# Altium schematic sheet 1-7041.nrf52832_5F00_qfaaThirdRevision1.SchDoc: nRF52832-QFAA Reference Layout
size A4; Revision: 1.1; SheetNumber: 1; SheetTotal: 1; DrawnBy: RUBR/KJP; DocumentSize: A4; PCAName: nRF52832-QFAA Reference Layout
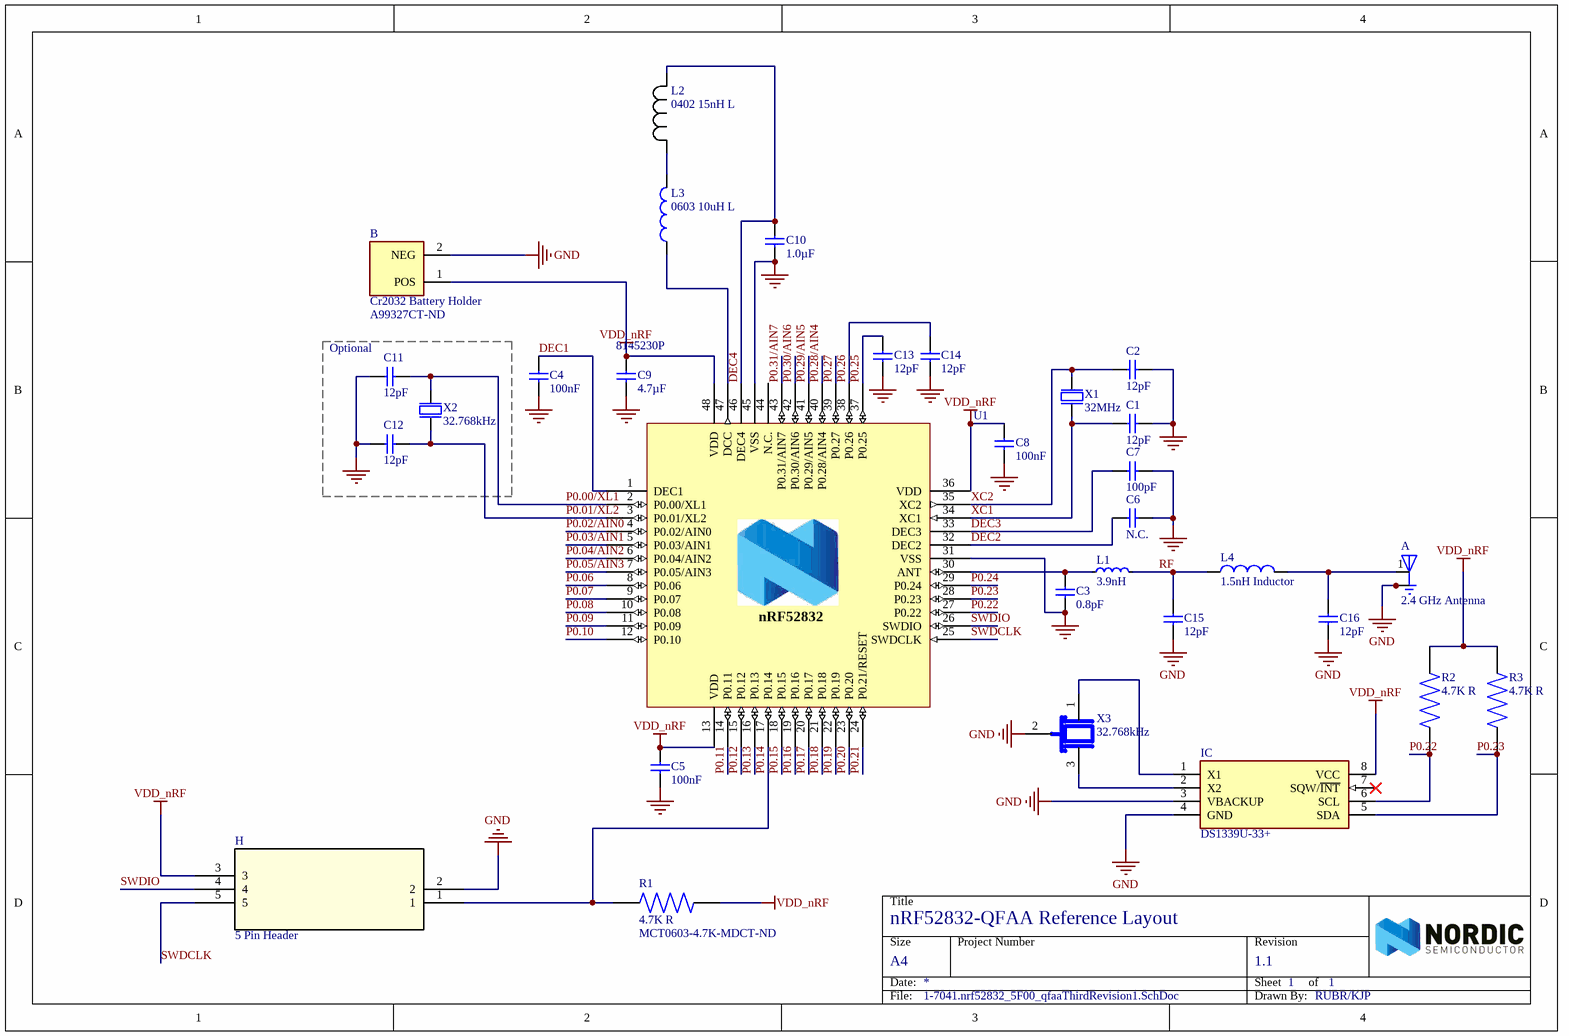
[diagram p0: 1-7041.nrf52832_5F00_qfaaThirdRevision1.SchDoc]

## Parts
A  2.4 GHz Antenna  [XDCR_2450AT42E010BE]
B  Cr2032 Battery Holder  Supplier Part Number 1: A99327CT-ND  [TE_796136-1]
C1  12pF  [CAPC1005X04L]
C2  12pF  [CAPC1005X04L]
C3  0.8pF  [CAPC1005X04L]
C4  100nF  [CAPC1005X04L]
C5  100nF  [CAPC1005X04L]
C6  N.C.  [CAPC1005X04L]
C7  100pF  [CAPC1005X04L]
C8  100nF  [CAPC1005X04L]
C9  4.7µF  Supplier Part Number 1: 8145230P  [CAPC1608X06L]
C10  1.0µF  [CAPC1608X06L]
C11  12pF  [CAPC1005X04L]
C12  12pF  [CAPC1005X04L]
C13  12pF  [CAPC1005X04L]
C14  12pF  [CAPC1005X04L]
C15  12pF  [CAPC1005X04L]
C16  12pF  [CAPC1005X04L]
H  5 Pin Header  [22-28-4052]
IC  DS1339U-33+  [SOP65P490X110-8N]
L1  3.9nH  [INDC1005X04L]
L2  0402 15nH L  [IND_1005_TDK]
L3  0603 10uH L  [INDC1608X100N]
L4  1.5nH Inductor  [INDC1005X55N]
R1  4.7K R  Supplier Part Number 1: MCT0603-4.7K-MDCT-ND  [RESC1508X55N]
R2  4.7K R  [RESC1508X55N]
R3  4.7K R  [RESC1508X55N]
U1  nRF52832-QFAA  [QFN40P600X600X90-48N]  (value not drawn)
X1  32MHz  [BT-XTAL_2016]
X2  32.768kHz  [XTAL_3215]
X3  32.768kHz  [XTAL_ECS-.327-6-1210B-N-TR]

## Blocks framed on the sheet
Optional: C11 C12 X2

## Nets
GND: A.3(GND) A.4(GND) B.2(NEG) C1.2 C2.2 C3.1 C4.2 C5.2 C6.1 C7.2 C8.2 C9.2 C10.1 C11.2 C12.2 C13.2 C14.2 C15.1 C16.1 H.2 IC.3(VBACKUP) IC.4(GND) U1.31(VSS) U1.45(VSS) U1.49(GND) X1.2(GND) X1.4(GND) X3.2(GND)
VDD_nRF: B.1(POS) C5.1 C8.1 C9.1 H.3 IC.8(VCC) R1.2 R2.2 R3.2 U1.13(VDD) U1.36(VDD) U1.48(VDD)
DEC1: C4.1 U1.1(DEC1)
DEC2: C6.2 U1.32(DEC2)
DEC3: C7.1 U1.33(DEC3)
DEC4: C10.2 L2.1 U1.46(DEC4)
P0.00/XL1: C11.1 U1.2(P0.00/XL1) X2.1(inp)
P0.01/XL2: C12.1 U1.3(P0.01/XL2) X2.2(out)
P0.02/AIN0: U1.4(P0.02/AIN0)
P0.03/AIN1: U1.5(P0.03/AIN1)
P0.04/AIN2: U1.6(P0.04/AIN2)
P0.05/AIN3: U1.7(P0.05/AIN3)
P0.06: U1.8(P0.06)
P0.07: U1.9(P0.07)
P0.08: U1.10(P0.08)
P0.09: U1.11(P0.09)
P0.10: U1.12(P0.10)
P0.11: U1.14(P0.11)
P0.12: U1.15(P0.12)
P0.13: U1.16(P0.13)
P0.14: H.1 R1.1 U1.17(P0.14)
P0.15: U1.18(P0.15)
P0.16: U1.19(P0.16)
P0.17: U1.20(P0.17)
P0.18: U1.21(P0.18)
P0.19: U1.22(P0.19)
P0.20: U1.23(P0.20)
P0.21: U1.24(P0.21/RESET)
P0.22: IC.6(SCL) R2.1 U1.27(P0.22)
P0.23: IC.5(SDA) R3.1 U1.28(P0.23)
P0.24: U1.29(P0.24)
P0.25: C13.1 U1.37(P0.25)
P0.26: C14.1 U1.38(P0.26)
P0.27: U1.39(P0.27)
P0.28/AIN4: U1.40(P0.28/AIN4)
P0.29/AIN5: U1.41(P0.29/AIN5)
P0.30/AIN6: U1.42(P0.30/AIN6)
P0.31/AIN7: U1.43(P0.31/AIN7)
RF: C15.2 L1.2 L4.1
SWDCLK: H.5 U1.25(SWDCLK)
SWDIO: H.4 U1.26(SWDIO)
XC1: C1.1 U1.34(XC1) X1.1(inp)
XC2: C2.1 U1.35(XC2) X1.3(out)
NetA_1: A.1(FEEDING) C16.2 L4.2
NetC3_2: C3.2 L1.1 U1.30(ANT)
NetIC_1: IC.1(X1) X3.1(IN/OUT)
NetIC_2: IC.2(X2) X3.3(OUT/IN)
NetL2_2: L2.2 L3.2
NetL3_1: L3.1 U1.47(DCC)

Not connected (* = marked no-connect by the designer): IC 7(SQW/~{INT})*; U1 44(N.C.)

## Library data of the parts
A = 2450AT42E010BE: JOHANSON TECHNOLOGY - 2450AT42E010BE - Chip-Antenne, Einzelband, 2.4GHz, 50 Ohm, 5mm x 2mm x 1.5mm; Number of Bands: 1; Max Power Dissipation: 2W
B = 796136-1: Surface Mount Battery Holder For 1; Leaf Spring Contact; Number_of_Positions: 2; MF: TE Connectivity
C1 C2 C11 C13 C14 = C0402-12p: Capacitor, NP0, ±2%; Note: 50V; Artikkelnr Noca: 20029159; Artikkelnr Simpro: N.A.
C3 = C0402-0.8p: Capacitor, NP0, ±5%; Note: 50V; Artikkelnr Noca: 20029147; Artikkelnr Simpro: N.A.
C4 C5 C8 = C0402-100n: Capacitor, X7R, ±10%; Note: 16V; Artikkelnr Noca: 20039200; Artikkelnr Simpro: N.A.
C6 = C0402-N.C.: Not mounted; Note: Chip Cap; Artikkelnr Noca: N.A.
C7 = C0402-100p: Capacitor, NP0, ±5%; Note: 50V; Artikkelnr Noca: 20029135; Artikkelnr Simpro: N.A.
C9 = C0603-4µ7: Capacitor, X5R, ±10%; Note: 6.3V; Artikkelnr Noca: 20069060; Artikkelnr Simpro: N.A.
C10 = C0603-1µ0: Capacitor, X7R, ±10%; Note: 16V; Artikkelnr Noca: 20039335; Artikkelnr Simpro: N.A.
C12 = CAP: Capacitor, NP0, ±2%; Part Number: C0402-12p; Note: 50V; Artikkelnr Noca: 20029159; Artikkelnr Simpro: N.A.
C15 C16 = CAP_0402: CAP CER 12PF 50V C0G/NPO 0402; Part Number: C0402-12p; Artikkelnr Noca: 20029159; Artikkelnr Simpro: N.A.; Tolerance: 5%; Dielectric: C0G
H = 22-28-4052: CONN HEADER 5POS .100 VERT TIN; Manufacturer: Molex; Vendor: Molex Connector Corporation; Built_By: EMA_UL_Team; SourceLibrary: Molex_2012-01-01_KK_Breakaway; Number of Contacts: 5; Gender: Male; Contact Resistance: 20mR; Connector Type: Male Pin; Current Rating: 4A; Voltage Rating: 250V; Max Voltage Rating (DC): 250.25kV; Pitch: 2.54mm; Glow Wire Compliant: Non-compliant
IC = DS1339U-33+: Real Time Clock Serial 8-Pin uMAX T/R; Manufacturer_Name: Maxim Integrated; Manufacturer: Maxim; Manufacturer Part Number: DS1339U-33+T&R; Time Format: HH:MM:SS; Operating Supply Voltage: 3.3V; Max Supply Voltage: 5.5V; Min Supply Voltage: 2.97V; Interface: I2C,Serial,2-Wire; Date Format: YY-MM-DD-dd
L1 = L0402-3n9: High frequency chip inductor ±5%; Manufacturer: Murata; Manufacturer Part Number: LQP15MN3N9B02D; Artikkelnr Noca: 33029151; Artikkelnr Simpro: N.A.
L2 = MLK1005S15NJT000: Ind RF Chip Unshielded Multi-Layer 15nH 5% 100MHz 7Q-Factor 300mA 0402 Punched Paper T/R; Manufacturer: TDK EPCOS; Vendor: TDK; Built_By: EMA_UL_Team; SourceLibrary: TDK_2015_05_22; Type: DEV; Core Material: Ceramic,Non-Magnetic; DC Resistance (DCR): 500mR; Self Resonant Frequency: 4GHz
L3 = CBMF1608T100K: Ind Power Chip Wirewound 10uH 10% 2.52MHz Ferrite 380mA 0603 T/R; MF: Taiyo Yuden; Self Resonant Frequency: 32MHz; DC Resistance (DCR): 468mR; Saturation Current: 115mA; Shielding: Unshielded
L4 = LQG15HS1N5S02D: Fixed Inductors 1.5nH +/-0.3 Hi-Freq; MF: Murata; Core Material: Air; DC Resistance (DCR): 100mR; Max DC Current: 300mA; Q Factor: 8; Shielding: Unshielded; Self Resonant Frequency: 6GHz; Test Frequency: 100MHz
R1-R3 = MCT0603MD4701DP500: RES SMD 4.7K OHM 0.5% 0.15W 0603; Manufacturer: Vishay; Resistance: 4.7kR; Power Rating: 125mW; Voltage Rating: 75V; Max Power Dissipation: 150mW; Temperature Coefficient: 25ppm/°C
U1 = nRF52832_QFAA: MCU 32-Bit ARM Cortex M4F RISC 512KB Flash 1.7V to 3.6V 48-Pin QFN EP Tray; Manufacturer: Nordic Semiconductor; Artikkelnr Noca: N.A.
X1 = XTAL_SMD2016_32MHz_8pF_General: XTAL SMD 2016, 32MHz, Cl=8pF, Total Tol: ±40ppm; Note: XTAL SMD 32.000MHz; Artikkelnr Noca: N.A.
X2 = XTAL_SMD3215_32.768kHz_9pF_General: XTAL SMD 3215, 32.768kHz, Cl=9pF, Total Tol: ±50ppm; Note: XTAL SMD 32.768kHz; Artikkelnr Noca: N.A.
X3 = ECS-.327-6-1210B-N-TR: Crystal 32.768kHz 6pF 4-Pin SMD T/R; Manufacturer: ECS International; MF: ECS Inc.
